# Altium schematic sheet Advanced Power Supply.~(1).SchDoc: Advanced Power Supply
size A4; Organization: BQR; Address1: Reliability Engineering; Address2: Optimized Maintenance; Address3: www.bqr.com; Address4: www.bqr-digital.com
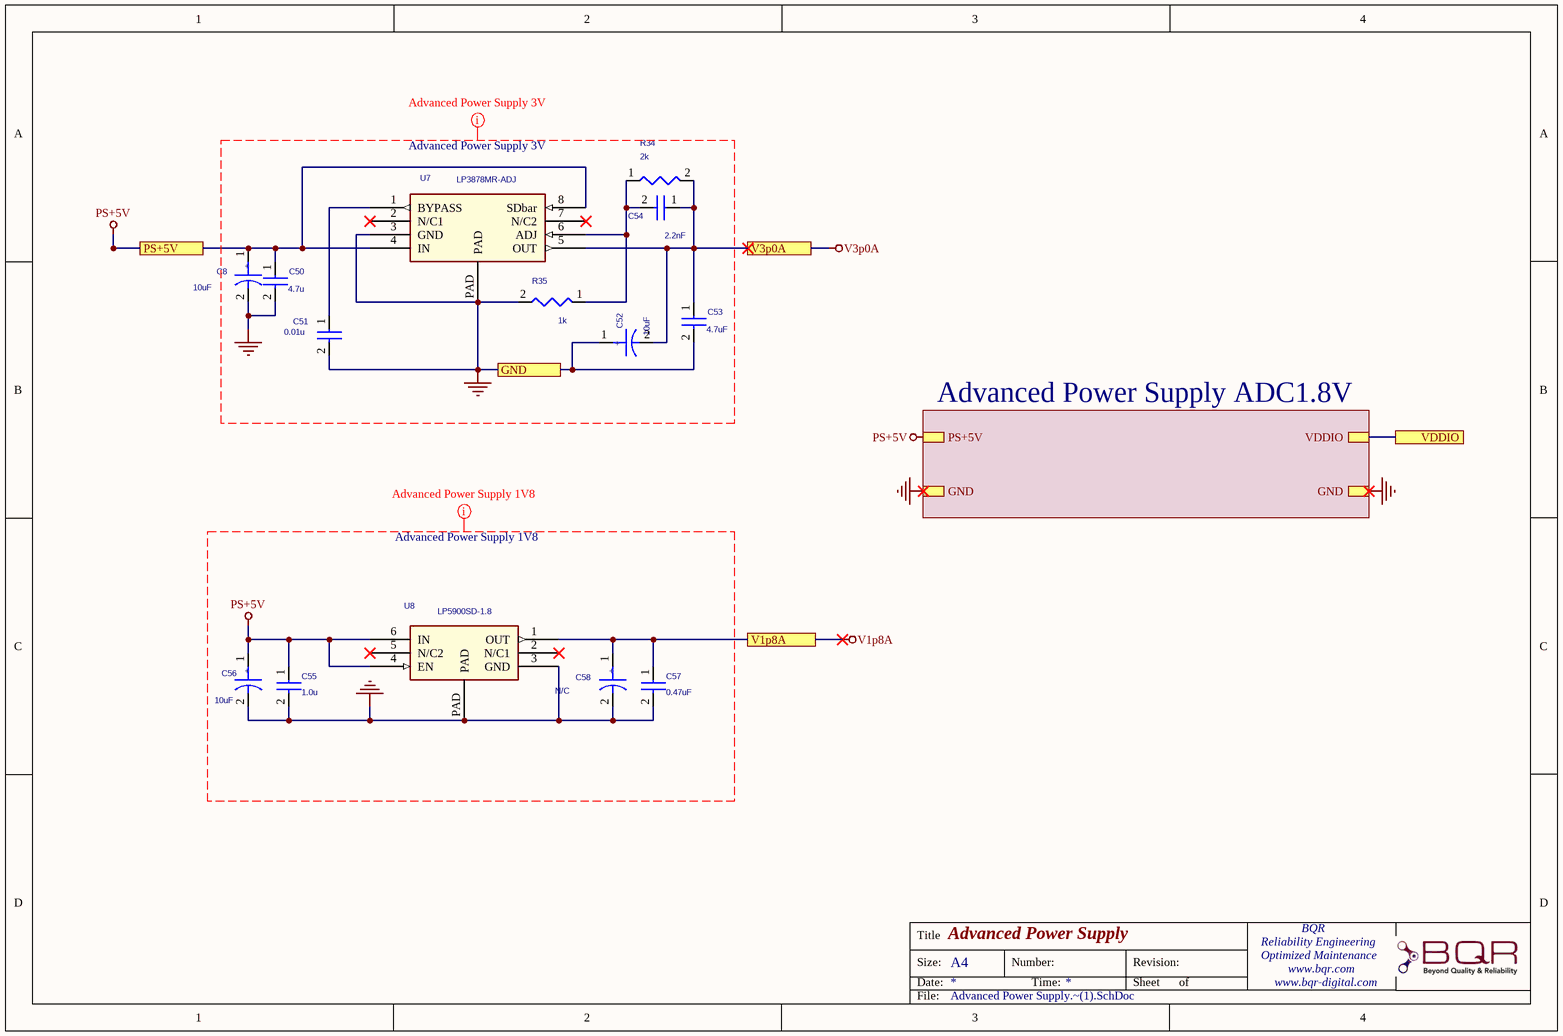
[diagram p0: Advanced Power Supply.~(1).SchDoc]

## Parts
C8  10uF  [cap_c-case]
C50  4.7u  [0603]
C51  0.01u  [0603]
C52  10uF  [cap_c-case]
C53  4.7uF  [0603]
C54  2.2nF  [0603]
C55  1.0u  [0603]
C56  10uF  [cap_c-case]
C57  0.47uF  [0603]
C58  N/C  [cap_c-case]
R34  2k  [0603]
R35  1k  [0603]
U7  LP3878MR-ADJ  [lp3878-adj_mra08a-psop]
U8  LP5900SD-1.8  [lp5900_sdb06a-llp6]

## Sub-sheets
Advanced Power Supply ADC1.8V = [7]Advanced Power Supply for ADC1.8V.SchDoc: VDDIO, PS+5V, GND, GND

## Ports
GND, PS+5V, V1p8A, V3p0A, VDDIO

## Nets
GND: C8.2 C50.2 C51.2 C52.1 C53.2 C55.2 C56.2 C57.2 C58.2 R35.2 U7.3(GND) U7.PAD U8.3(GND) U8.PAD ; port GND, sheet Advanced Power Supply ADC1.8V/GND, sheet Advanced Power Supply ADC1.8V/GND
PS+5V: C8.1 C50.1 C55.1 C56.1 U7.4(IN) U7.8(SDbar) U8.4(EN) U8.6(IN) ; port PS+5V, sheet Advanced Power Supply ADC1.8V/PS+5V
V1p8A: C57.1 C58.1 U8.1(OUT) ; port V1p8A
V3p0A: C52.2 C53.1 C54.1 R34.2 U7.5(OUT) ; port V3p0A
VDDIO: port VDDIO, sheet Advanced Power Supply ADC1.8V/VDDIO
NetC51_1: C51.1 U7.1(BYPASS)
NetC54_2: C54.2 R34.1 R35.1 U7.6(ADJ)

Not connected (* = marked no-connect by the designer): U7 2(N/C1)* 7(N/C2)*; U8 2(N/C1)* 5(N/C2)*

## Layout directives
CompClassName: Advanced Power Supply 3V: GND
CompClassName: Advanced Power Supply 1V8: GND, PS+5V

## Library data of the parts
C8 = Cap_Polar_1: CAP TANT 10UF 20V 10% 2312; Manufacturer P/N: TAJC106K020R; Manufacturer: AVX; fiX_Manuf: Murata; Catalog Number: CAP00001; SDTA_I(Isurge): 0.001; SDTA_V(Voltage): 5; fiX_Func: Advanced Power Supply 3V A (11)
C50 = Capacitor_3: CAP CER 4.7UF 6.3V X5R 0603; Manufacturer: Panasonic; Manufacturer P/N: ECJ-1VB0J475M; Catalog Number: CAP00017; SDTA_V(Voltage): 5; fiX_Func: Advanced Power Supply 3V A (11)
C51 = Capacitor_3: CAP CER 10000PF 50V X7R 0603; Manufacturer P/N: ECJ-1VB1H103K; Manufacturer: Panasonic; fiX_Manuf: AVX; Catalog Number: CAP00018; fiX_Func: Advanced Power Supply 3V A (11); SDTA_V(Voltage): 5
C52 = Cap_Polar_1: CAP TANT 10UF 20V 10% 2312; Manufacturer P/N: TAJC106K020R; Manufacturer: AVX; fiX_Manuf: Murata; Catalog Number: CAP00001; SDTA_V(Voltage): 15; fiX_Func: Advanced Power Supply 3V A (11); SDTA_P(): 3
C53 = Capacitor_3: CAP CER 4.7UF 6.3V X5R 0603; Manufacturer P/N: ECJ-1VB0J475M; Manufacturer: Panasonic; Catalog Number: CAP00017; SDTA_V(Voltage): 15; fiX_Func: Advanced Power Supply 3V A (11); SDTA_P(): 3
C54 = Cap_1: CAP CER 2200PF 50V X7R 0603; Manufacturer P/N: ECJ-1VB1H222K; Manufacturer: Panasonic; fiX_Manuf: Murata; Catalog Number: CAP00019; fiX_Func: Advanced Power Supply 3V A (11); SDTA_V(Voltage): 6
C55 = Capacitor_3: CAP CER 1UF 16V X7R 0603; Manufacturer: Murata; Manufacturer P/N: GRM188R71C105KA12D; fiX_Manuf: AVX; Catalog Number: CAP00028; SDTA_V(Voltage): 5; fiX_Func: Advanced Power Supply 1.8V (3)
C56 = Cap_Polar_1: CAP TANT 10UF 20V 10% 2312; Manufacturer P/N: TAJC106K020R; Manufacturer: AVX; fiX_Manuf: Murata; Catalog Number: CAP00001; SDTA_I(Isurge): 0.001; SDTA_V(Voltage): 5; fiX_Func: Advanced Power Supply 1.8V (3)
C57 = Capacitor_3: CAP CER 0.47UF 6.3V X5R 0603; Manufacturer P/N: ECJ-1VB0J474K; Manufacturer: Panasonic; fiX_Manuf: AVX; Catalog Number: CAP00016; SDTA_V(Voltage): 1.8; fiX_Func: Advanced Power Supply 1.8V (3)
C58 = Cap_Polar_1: CAP TANT 10UF 20V 10% 2312; Manufacturer P/N: TAJC106K020R; Manufacturer: AVX; fiX_Manuf: Murata; Catalog Number: CAP00001; SDTA_V(Voltage): 1.8; fiX_Func: Advanced Power Supply 1.8V (3)
R34 = Resistor_3: RES SMD 2K OHM 1% 1/10W 0603; Manufacturer P/N: CRCW06032K00FKEA; Manufacturer: Vishay; Catalog Number: RES00011; fiX_Func: Advanced Power Supply 3V A (11); SDTA_P(Power): 0.018; SDTA_V(Voltage): 6; Filename: AdvPwr3V
R35 = Resistor_3: RES SMD 1K OHM 1% 1/10W 0603; Manufacturer P/N: CRCW06031K00FKEA; Manufacturer: Vishay; Catalog Number: RES00010; fiX_Func: Advanced Power Supply 3V A (11); Filename: AdvPwr3V
U7 = LP3878MR-ADJ_4: Linear Voltage Regulator IC Positive Adjustable 1 Output 1 V ~ 5.5 V 800mA 8-SO PowerPad; Manufacturer: Texas Instruments; Manufacturer P/N: LP3878MR-ADJ/NOPB; Catalog Number: IC00030; fiX_Func: Advanced Power Supply 3V A (11); SDTA_I(Iout): 2; SDTA_V(Vsupply): 20; Filename: AdvPwr3V
U8 = LP5900SD-1_0.8: IC REG LDO 1.8V 0.15A 6WSON; Manufacturer: Texas Instruments; Manufacturer P/N: LP5900SD-1.8/NOPB; Catalog Number: IC00031; fiX_Func: Advanced Power Supply 1.8V (3); Filename: AdvPwr1V8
